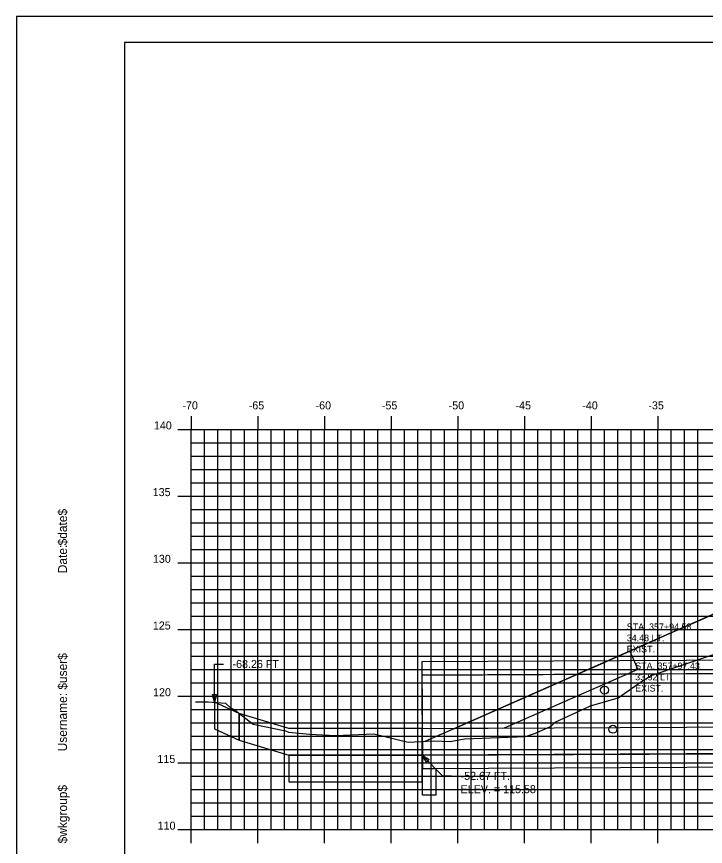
# Model space of a CAD drawing. Extents: x 1145859 to 1146029, y 608981 to 609091.
# Drawn here: x 1145859.3 to 1145911, y 609029.1 to 609091.3 of the extents above; entities that cross this region are included whole.
import ezdxf

# ---------------------------------------------------------------- set-up
doc = ezdxf.new("R2010")
doc.units = 0
for name, color, linetype in [('BORDER', 7, 'Continuous'), ('D_Drainage_Culvert', 7, 'Continuous'), ('D_Roadway_SlopeLines', 7, 'Continuous'), ('D_Text_Monospaced', 7, 'Continuous'), ('D_Text_Standard', 7, 'Continuous'), ('H_V ANNOTATION', 7, 'Continuous'), ('MAJOR', 7, 'Continuous'), ('MINOR', 7, 'Continuous'), ('PATTERNING', 7, 'Continuous'), ('PLOT BOUNDARY', 7, 'Continuous'), ('S_Drainage_Invert', 7, 'Continuous'), ('S_Roadway_Centerline', 7, 'Continuous')]:
    doc.layers.add(name, color=color, linetype=linetype)

msp = doc.modelspace()

# ---------------------------------------------------------------- linework, layer by layer
msp.add_lwpolyline([(1145889.938, 609036.955), (1145891.203, 609037.512), (1145891.277, 609037.545), (1145892.978, 609038.294), (1145893.17, 609038.379), (1145894.751, 609039.075), (1145895.064, 609039.213), (1145896.521, 609039.855), (1145896.958, 609040.047), (1145898.287, 609040.633), (1145898.851, 609040.881), (1145900.056, 609041.412), (1145900.745, 609041.716), (1145901.826, 609042.192), (1145902.639, 609042.55), (1145903.591, 609042.97), (1145904.532, 609043.385), (1145904.684, 609043.452), (1145904.865, 609043.532), (1145905.557, 609043.837), (1145906.426, 609044.22), (1145907.149, 609044.539), (1145908.32, 609045.055), (1145908.889, 609045.306), (1145910.214, 609045.89), (1145910.608, 609046.064), (1145912.107, 609046.725)])
at = {"layer": 'BORDER'}
msp.add_lwpolyline([(1145867.402, 608984.335), (1146027.402, 608984.335), (1146027.402, 609089.335), (1145867.402, 609089.335)], close=True, dxfattribs=at)
at = {"layer": 'D_Drainage_Culvert'}
for points in [[(1145889.737, 609034.915), (1145993.735, 609035.435), (1145993.695, 609043.435), (1145889.697, 609042.915)], [(1145889.732, 609035.915), (1145993.73, 609036.435), (1145993.7, 609042.435), (1145889.702, 609041.915)], [(1145889.737, 609034.915), (1145890.737, 609034.92), (1145890.747, 609032.92), (1145889.747, 609032.915)]]:
    msp.add_lwpolyline(points, close=True, dxfattribs=at)
at = {"layer": 'D_Roadway_SlopeLines'}
msp.add_lwpolyline([(1145914.209, 609047.653), (1145892.142, 609037.927)], dxfattribs=at)
at = {"layer": 'D_Text_Standard'}
for points in [[(1145874.142, 609039.883), (1145874.14, 609042.75), (1145874.82, 609042.75)], [(1145889.732, 609035.915), (1145891.242, 609034.368), (1145891.922, 609034.368)]]:
    msp.add_lwpolyline(points, dxfattribs=at)
for points in [[(1145874.142, 609039.883), (1145873.996, 609040.465), (1145874.287, 609040.465)], [(1145889.732, 609035.915), (1145890.242, 609035.6), (1145890.034, 609035.397)]]:
    msp.add_lwpolyline(points, close=True, dxfattribs=at)
at = {"layer": 'MAJOR'}
for p, q in [((1145872.402, 609061.337), (1145872.402, 609060.335)), ((1145877.402, 609061.337), (1145877.402, 609060.335)), ((1145882.402, 609061.337), (1145882.402, 609060.335)), ((1145887.402, 609061.337), (1145887.402, 609060.335)), ((1145892.402, 609061.337), (1145892.402, 609060.335)), ((1145897.402, 609061.337), (1145897.402, 609060.335)), ((1145902.402, 609061.337), (1145902.402, 609060.335)), ((1145907.402, 609061.337), (1145907.402, 609060.335)), ((1145871.4, 609060.335), (1145872.402, 609060.335)), ((1145872.402, 609060.335), (1146012.402, 609060.335)), ((1145872.402, 609030.335), (1145872.402, 609060.335)), ((1145872.402, 609030.335), (1145872.402, 609060.335)), ((1145872.402, 609060.335), (1146012.402, 609060.335)), ((1145877.402, 609030.335), (1145877.402, 609060.335)), ((1145882.402, 609030.335), (1145882.402, 609060.335)), ((1145887.402, 609030.335), (1145887.402, 609060.335)), ((1145892.402, 609030.335), (1145892.402, 609060.335)), ((1145897.402, 609030.335), (1145897.402, 609060.335)), ((1145902.402, 609030.335), (1145902.402, 609060.335)), ((1145907.402, 609030.335), (1145907.402, 609060.335)), ((1145871.4, 609055.335), (1145872.402, 609055.335)), ((1145872.402, 609055.335), (1146012.402, 609055.335)), ((1145871.4, 609050.335), (1145872.402, 609050.335)), ((1145872.402, 609050.335), (1146012.402, 609050.335)), ((1145871.4, 609045.335), (1145872.402, 609045.335)), ((1145872.402, 609045.335), (1146012.402, 609045.335)), ((1145871.4, 609040.335), (1145872.402, 609040.335)), ((1145872.402, 609040.335), (1146012.402, 609040.335)), ((1145871.4, 609035.335), (1145872.402, 609035.335)), ((1145872.402, 609035.335), (1146012.402, 609035.335)), ((1145871.4, 609030.335), (1145872.402, 609030.335)), ((1145872.402, 609030.335), (1146012.402, 609030.335)), ((1145872.402, 609030.335), (1146012.402, 609030.335)), ((1145872.402, 609029.333), (1145872.402, 609030.335)), ((1145877.402, 609029.333), (1145877.402, 609030.335)), ((1145882.402, 609029.333), (1145882.402, 609030.335)), ((1145887.402, 609029.333), (1145887.402, 609030.335)), ((1145892.402, 609029.333), (1145892.402, 609030.335)), ((1145897.402, 609029.333), (1145897.402, 609030.335)), ((1145902.402, 609029.333), (1145902.402, 609030.335)), ((1145907.402, 609029.333), (1145907.402, 609030.335))]:
    msp.add_line(p, q, dxfattribs=at)
at = {"layer": 'MINOR'}
for p, q in [((1145872.402, 609030.335), (1145872.402, 609060.335)), ((1145873.402, 609030.335), (1145873.402, 609060.335)), ((1145874.402, 609030.335), (1145874.402, 609060.335)), ((1145875.402, 609030.335), (1145875.402, 609060.335)), ((1145876.402, 609030.335), (1145876.402, 609060.335)), ((1145878.402, 609030.335), (1145878.402, 609060.335)), ((1145879.402, 609030.335), (1145879.402, 609060.335)), ((1145880.402, 609030.335), (1145880.402, 609060.335)), ((1145881.402, 609030.335), (1145881.402, 609060.335)), ((1145883.402, 609030.335), (1145883.402, 609060.335)), ((1145884.402, 609030.335), (1145884.402, 609060.335)), ((1145885.402, 609030.335), (1145885.402, 609060.335)), ((1145886.402, 609030.335), (1145886.402, 609060.335)), ((1145888.402, 609030.335), (1145888.402, 609060.335)), ((1145889.402, 609030.335), (1145889.402, 609060.335)), ((1145890.402, 609030.335), (1145890.402, 609060.335)), ((1145891.402, 609030.335), (1145891.402, 609060.335)), ((1145893.402, 609030.335), (1145893.402, 609060.335)), ((1145894.402, 609030.335), (1145894.402, 609060.335)), ((1145895.402, 609030.335), (1145895.402, 609060.335)), ((1145896.402, 609030.335), (1145896.402, 609060.335)), ((1145898.402, 609030.335), (1145898.402, 609060.335)), ((1145899.402, 609030.335), (1145899.402, 609060.335)), ((1145900.402, 609030.335), (1145900.402, 609060.335)), ((1145901.402, 609030.335), (1145901.402, 609060.335)), ((1145903.402, 609030.335), (1145903.402, 609060.335)), ((1145904.402, 609030.335), (1145904.402, 609060.335)), ((1145905.402, 609030.335), (1145905.402, 609060.335)), ((1145906.402, 609030.335), (1145906.402, 609060.335)), ((1145908.402, 609030.335), (1145908.402, 609060.335)), ((1145909.402, 609030.335), (1145909.402, 609060.335)), ((1145910.402, 609030.335), (1145910.402, 609060.335)), ((1145872.402, 609059.335), (1146012.402, 609059.335)), ((1145872.402, 609059.335), (1145873.404, 609059.335)), ((1145872.402, 609058.335), (1146012.402, 609058.335)), ((1145872.402, 609058.335), (1145873.404, 609058.335)), ((1145872.402, 609057.335), (1146012.402, 609057.335)), ((1145872.402, 609057.335), (1145873.404, 609057.335)), ((1145872.402, 609056.335), (1146012.402, 609056.335)), ((1145872.402, 609056.335), (1145873.404, 609056.335)), ((1145872.402, 609054.335), (1146012.402, 609054.335)), ((1145872.402, 609054.335), (1145873.404, 609054.335)), ((1145872.402, 609053.335), (1146012.402, 609053.335)), ((1145872.402, 609053.335), (1145873.404, 609053.335)), ((1145872.402, 609052.335), (1146012.402, 609052.335)), ((1145872.402, 609052.335), (1145873.404, 609052.335)), ((1145872.402, 609051.335), (1146012.402, 609051.335)), ((1145872.402, 609051.335), (1145873.404, 609051.335)), ((1145872.402, 609049.335), (1146012.402, 609049.335)), ((1145872.402, 609049.335), (1145873.404, 609049.335)), ((1145872.402, 609048.335), (1146012.402, 609048.335)), ((1145872.402, 609048.335), (1145873.404, 609048.335)), ((1145872.402, 609047.335), (1146012.402, 609047.335)), ((1145872.402, 609047.335), (1145873.404, 609047.335)), ((1145872.402, 609046.335), (1146012.402, 609046.335)), ((1145872.402, 609046.335), (1145873.404, 609046.335)), ((1145872.402, 609044.335), (1146012.402, 609044.335)), ((1145872.402, 609044.335), (1145873.404, 609044.335)), ((1145872.402, 609043.335), (1146012.402, 609043.335)), ((1145872.402, 609043.335), (1145873.404, 609043.335)), ((1145872.402, 609042.335), (1146012.402, 609042.335)), ((1145872.402, 609042.335), (1145873.404, 609042.335)), ((1145872.402, 609041.335), (1146012.402, 609041.335)), ((1145872.402, 609041.335), (1145873.404, 609041.335)), ((1145872.402, 609039.335), (1146012.402, 609039.335)), ((1145872.402, 609039.335), (1145873.404, 609039.335)), ((1145872.402, 609038.335), (1146012.402, 609038.335)), ((1145872.402, 609038.335), (1145873.404, 609038.335)), ((1145872.402, 609037.335), (1146012.402, 609037.335)), ((1145872.402, 609037.335), (1145873.404, 609037.335)), ((1145872.402, 609036.335), (1146012.402, 609036.335)), ((1145872.402, 609036.335), (1145873.404, 609036.335)), ((1145872.402, 609034.335), (1146012.402, 609034.335)), ((1145872.402, 609034.335), (1145873.404, 609034.335)), ((1145872.402, 609033.335), (1146012.402, 609033.335)), ((1145872.402, 609033.335), (1145873.404, 609033.335)), ((1145872.402, 609032.335), (1146012.402, 609032.335)), ((1145872.402, 609032.335), (1145873.404, 609032.335)), ((1145872.402, 609031.335), (1146012.402, 609031.335)), ((1145872.402, 609031.335), (1145873.404, 609031.335))]:
    msp.add_line(p, q, dxfattribs=at)
at = {"layer": 'PATTERNING'}
for p, q in [((1145889.702, 609041.915), (1145993.7, 609042.435)), ((1145876.002, 609037.037), (1145876.002, 609039.037)), ((1145993.73, 609036.435), (1145889.732, 609035.915)), ((1145889.732, 609035.915), (1145993.732, 609036.435)), ((1145879.732, 609035.915), (1145879.732, 609033.915)), ((1145889.732, 609035.915), (1145889.737, 609034.915))]:
    msp.add_line(p, q, dxfattribs=at)
for points in [[(1145993.695, 609043.435), (1145889.697, 609042.915), (1145889.702, 609041.915)], [(1145876.002, 609039.037), (1145874.142, 609039.883), (1145874.142, 609037.883), (1145876.002, 609037.037)], [(1145879.732, 609037.915), (1145876.002, 609039.037), (1145876.002, 609037.037), (1145879.732, 609035.915)], [(1145879.732, 609035.915), (1145889.732, 609035.915), (1145889.732, 609037.915), (1145879.732, 609037.915)], [(1145889.737, 609034.915), (1145993.735, 609035.435), (1145993.73, 609036.435)], [(1145879.732, 609033.915), (1145889.732, 609033.915), (1145889.732, 609035.915), (1145879.732, 609035.915)]]:
    msp.add_lwpolyline(points, dxfattribs=at)
for points in [[(1145892.142, 609037.927), (1145903.459, 609042.915), (1145905.291, 609043.718), (1145905.893, 609042.345), (1145895.862, 609037.946)], [(1145889.732, 609035.915), (1145889.722, 609037.915), (1145993.72, 609038.435), (1145993.73, 609036.435)]]:
    msp.add_lwpolyline(points, close=True, dxfattribs=at)
at = {"layer": 'PLOT BOUNDARY'}
msp.add_lwpolyline([(1145859.308, 608981.276), (1146029.308, 608981.276), (1146029.308, 609091.276), (1145859.308, 609091.276)], close=True, dxfattribs=at)
at = {"layer": 'S_Drainage_Invert'}
for centre in [(1145903.393, 609040.79), (1145904.026, 609037.862)]:
    msp.add_circle(centre, 0.3, dxfattribs=at)
at = {"layer": 'S_Roadway_Centerline'}
msp.add_lwpolyline([(1145872.724, 609039.92), (1145873.668, 609039.916), (1145874.964, 609039.826), (1145875.345, 609039.463), (1145875.625, 609039.329), (1145877.036, 609038.235), (1145879.462, 609037.73), (1145879.707, 609037.653), (1145881.296, 609037.502), (1145883.232, 609037.39), (1145886.096, 609037.526), (1145888.678, 609036.899), (1145890.574, 609036.989), (1145891.825, 609036.934), (1145892.891, 609037.152), (1145897.477, 609037.316), (1145898.222, 609037.568), (1145899.4, 609038.087), (1145899.697, 609038.39), (1145902.351, 609039.607), (1145904.408, 609040.226), (1145906.156, 609041.432), (1145906.881, 609041.89), (1145913.944, 609044.257)], dxfattribs=at)

# ---------------------------------------------------------------- texts
at = {"layer": 'BORDER'}
for s, p in [('$date$', (1145863.087, 609051.64)), ('Date:', (1145863.087, 609049.552)), ('$user$', (1145863.087, 609040.827)), ('Username:', (1145863.087, 609036.203)), ('$wkgroup$', (1145863.087, 609029.305))]:
    msp.add_text(s, height=0.6696, rotation=90, dxfattribs=at).set_placement(p)
at = {"layer": 'D_Text_Monospaced'}
for s, height, p in [('STA. 357+94.58', 0.49998, (1145905.059, 609045.288)), ('34.48 LT.', 0.5, (1145905.059, 609044.454)), ('EXIST. ', 0.5, (1145905.059, 609043.614)), ('STA. 357+97.43', 0.49998, (1145905.693, 609042.36)), ('33.92 LT.', 0.5, (1145905.693, 609041.526)), ('EXIST. ', 0.5, (1145905.693, 609040.686))]:
    msp.add_text(s, height=height, dxfattribs=at).set_placement(p)
at = {"layer": 'D_Text_Standard'}
for s, p in [('-68.26 FT', (1145875.5, 609042.45)), ('-52.67 FT.', (1145892.602, 609034.068)), ('ELEV. = 115.58', (1145892.602, 609033.068))]:
    msp.add_text(s, height=0.6, dxfattribs=at).set_placement(p)
at = {"layer": 'H_V ANNOTATION'}
for s, p in [('-70', (1145871.743, 609061.835)), ('-65', (1145876.719, 609061.835)), ('-60', (1145881.727, 609061.835)), ('-55', (1145886.698, 609061.835)), ('-50', (1145891.706, 609061.835)), ('-45', (1145896.719, 609061.835)), ('-40', (1145901.727, 609061.835)), ('-35', (1145906.682, 609061.835)), ('140', (1145869.606, 609060.335)), ('135', (1145869.516, 609055.335)), ('130', (1145869.532, 609050.335)), ('125', (1145869.526, 609045.335)), ('120', (1145869.542, 609040.335)), ('115', (1145869.869, 609035.335)), ('110', (1145869.885, 609030.335))]:
    msp.add_text(s, height=0.6, dxfattribs=at).set_placement(p)
at = {"layer": 'MAJOR'}
msp.add_text('-', height=0.006, dxfattribs=at).set_placement((1145872.397, 609030.335))

doc.saveas('drawing.dxf')
